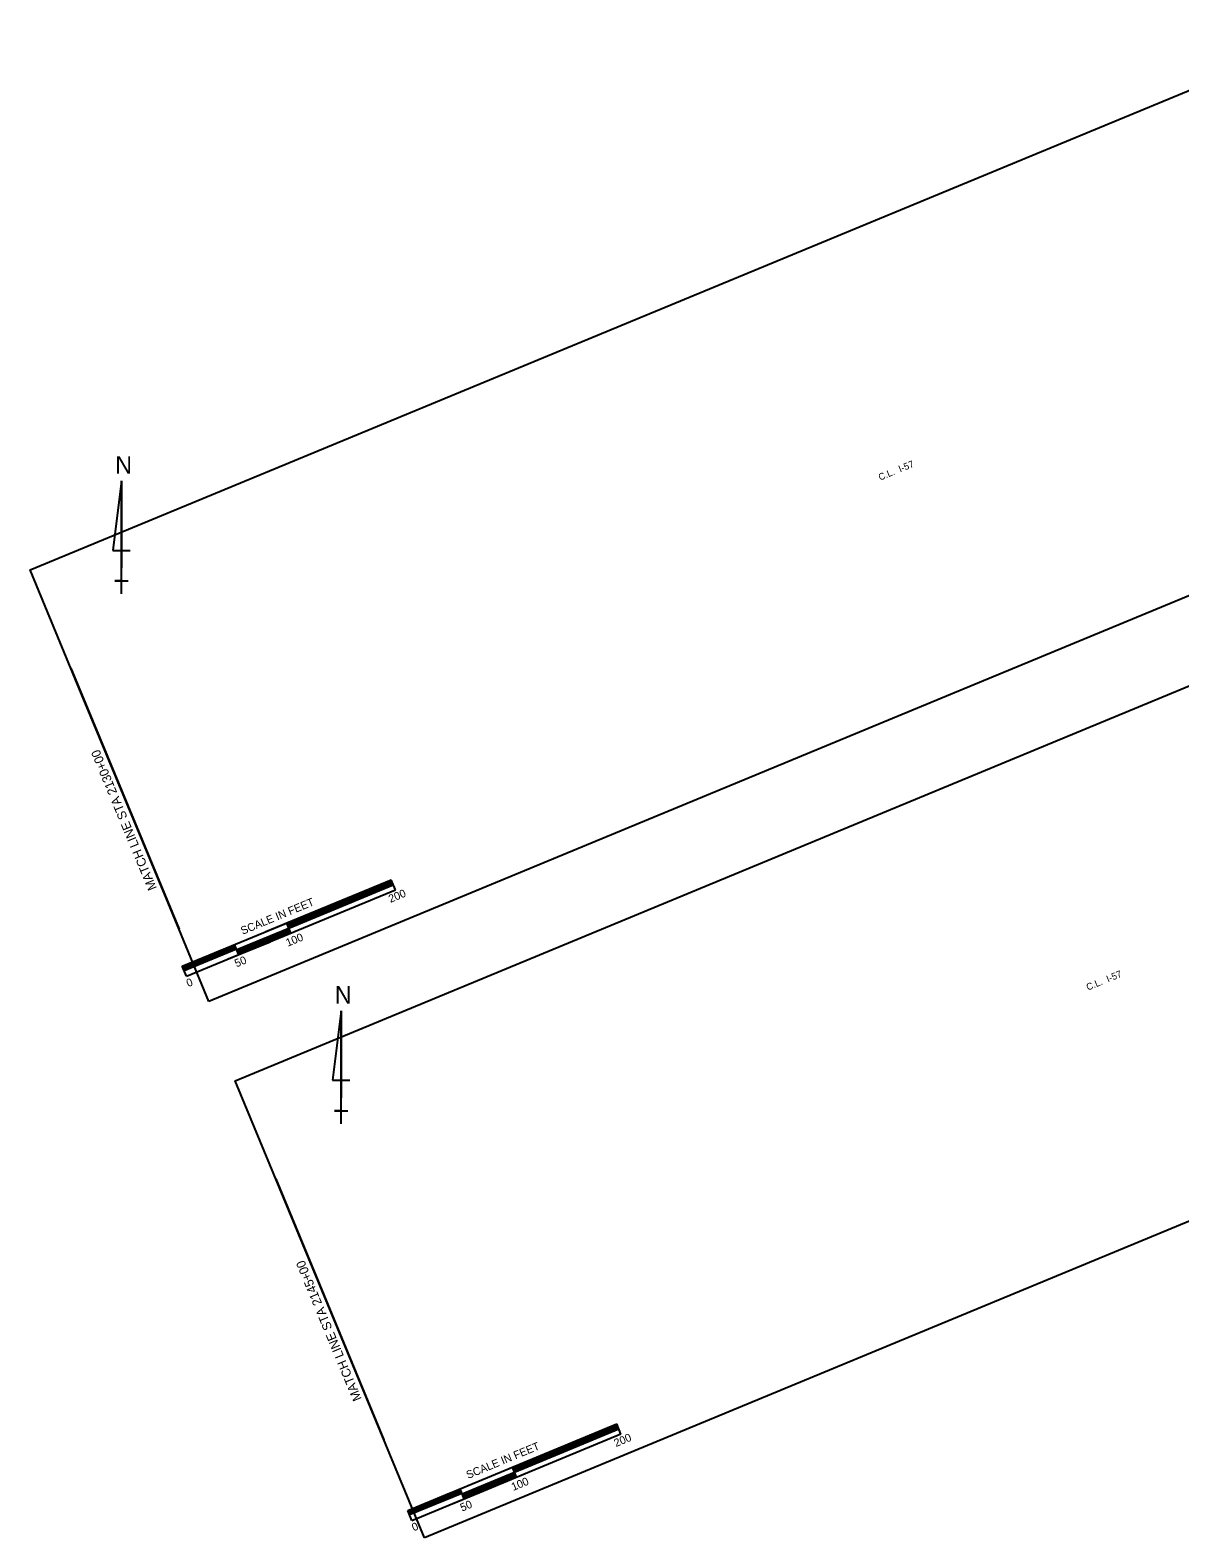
# Model space of a CAD drawing. Extents: x 1718926 to 1720959, y 766362 to 768034.
# Drawn here: x 1718926 to 1719943, y 766362 to 767696 of the extents above; entities that cross this region are included whole.
import ezdxf

# ---------------------------------------------------------------- set-up
doc = ezdxf.new("R2010")
doc.units = 0
for name, color, linetype in [('19', 7, 'Continuous'), ('2', 7, 'Continuous'), ('20', 7, 'Continuous'), ('3', 7, 'Continuous'), ('5', 7, 'Continuous')]:
    doc.layers.add(name, color=color, linetype=linetype)

msp = doc.modelspace()

# ---------------------------------------------------------------- linework, layer by layer
at = {"layer": '19'}
for p, q in [((1718961.8, 767131.7), (1719057.5, 766900.8)), ((1719143, 766679.8), (1719238.7, 766448.9))]:
    msp.add_line(p, q, dxfattribs=at)
at = {"layer": '2'}
for points in [[(1719084, 766836.7), (1719047.9, 766923.9), (1718971.4, 767108.6), (1718925.9, 767218.5), (1720031.8, 767676.5), (1720208.6, 767696.1), (1720357.2, 767682.7), (1720433.7, 767497.9), (1720473.4, 767413.9), (1720476, 767413.2)], [(1719274.6, 766362.1), (1719107.1, 766766.6), (1720213, 767224.6), (1720510, 767294), (1720538.4, 767230.8), (1720615, 767046), (1720666.6, 766938.7)]]:
    msp.add_lwpolyline(points, close=True, dxfattribs=at)
at = {"layer": '20'}
for p, q in [((1719134.3, 766898.5), (1719245.2, 766944.4)), ((1719153.1, 766905.4), (1719245.5, 766943.7)), ((1719153.4, 766904.7), (1719245.8, 766942.9)), ((1719153.7, 766903.9), (1719246.1, 766942.2)), ((1719154, 766903.2), (1719246.4, 766941.5)), ((1719154.3, 766902.5), (1719246.7, 766940.7)), ((1719154.7, 766901.7), (1719247, 766940)), ((1719248.9, 766935.5), (1719245.2, 766944.4)), ((1719060.4, 766867.9), (1719208.2, 766929.1)), ((1719064.1, 766859), (1719248.9, 766935.6)), ((1719154.7, 766901.7), (1719210.1, 766924.7)), ((1719108.5, 766882.6), (1719154.7, 766901.7)), ((1719108.8, 766881.8), (1719155, 766901)), ((1719109.1, 766881.1), (1719155.3, 766900.2)), ((1719109.4, 766880.4), (1719155.6, 766899.5)), ((1719109.7, 766879.6), (1719155.9, 766898.8)), ((1719156.5, 766897.3), (1719152.8, 766906.1)), ((1719060.7, 766867.1), (1719106.9, 766886.3)), ((1719061, 766866.4), (1719107.2, 766885.5)), ((1719101.1, 766874.3), (1719138, 766889.6)), ((1719110.3, 766878.1), (1719106.6, 766887)), ((1719110, 766878.9), (1719156.2, 766898)), ((1719060.4, 766867.9), (1719097.4, 766883.2)), ((1719061.3, 766865.7), (1719107.5, 766884.8)), ((1719061.7, 766864.9), (1719107.8, 766884.1)), ((1719062, 766864.2), (1719108.2, 766883.3)), ((1719064.1, 766859), (1719060.4, 766867.9)), ((1719333.8, 766417), (1719444.6, 766462.9)), ((1719352.6, 766423.9), (1719445, 766462.2)), ((1719352.9, 766423.2), (1719445.3, 766461.5)), ((1719353.2, 766422.4), (1719445.6, 766460.7)), ((1719353.5, 766421.7), (1719445.9, 766460)), ((1719353.8, 766421), (1719446.2, 766459.2)), ((1719354.1, 766420.2), (1719446.5, 766458.5)), ((1719448.3, 766454), (1719444.7, 766462.9)), ((1719259.9, 766386.4), (1719407.7, 766447.6)), ((1719263.5, 766377.5), (1719448.3, 766454.1)), ((1719354.1, 766420.2), (1719409.5, 766443.2)), ((1719307.9, 766401.1), (1719354.1, 766420.2)), ((1719308.2, 766400.4), (1719354.4, 766419.5)), ((1719308.5, 766399.6), (1719354.7, 766418.8)), ((1719355.9, 766415.8), (1719352.3, 766424.7)), ((1719300.5, 766392.8), (1719337.5, 766408.1)), ((1719309.7, 766396.7), (1719306.1, 766405.5)), ((1719308.8, 766398.9), (1719355, 766418)), ((1719309.1, 766398.1), (1719355.3, 766417.3)), ((1719309.4, 766397.4), (1719355.6, 766416.5)), ((1719259.9, 766386.4), (1719296.8, 766401.7)), ((1719260.2, 766385.7), (1719306.4, 766404.8)), ((1719260.5, 766384.9), (1719306.7, 766404.1)), ((1719260.8, 766384.2), (1719307, 766403.3)), ((1719261.1, 766383.4), (1719307.3, 766402.6)), ((1719261.4, 766382.7), (1719307.6, 766401.8)), ((1719263.5, 766377.5), (1719259.9, 766386.4))]:
    msp.add_line(p, q, dxfattribs=at)
at = {"layer": '3'}
for p, q in [((1719006.7, 767297.4), (1718999, 767235.8)), ((1719006.7, 767197.4), (1719006.7, 767297.4)), ((1719006.7, 767297.4), (1719006.7, 767220.5)), ((1718999, 767235.8), (1719014.4, 767235.8)), ((1719006.7, 767197.4), (1719006.7, 767220.5)), ((1719006.7, 767208.9), (1719000.9, 767208.9)), ((1719000.9, 767208.9), (1719012.5, 767208.9)), ((1719006.7, 767197.4), (1719006.7, 767208.9)), ((1719200.9, 766828.5), (1719193.2, 766767)), ((1719200.9, 766728.5), (1719200.9, 766828.5)), ((1719200.9, 766828.5), (1719200.9, 766751.6)), ((1719193.2, 766767), (1719208.6, 766767)), ((1719200.9, 766740.1), (1719195.1, 766740.1)), ((1719195.1, 766740.1), (1719206.7, 766740.1)), ((1719200.9, 766728.5), (1719200.9, 766751.6)), ((1719200.9, 766728.5), (1719200.9, 766740.1))]:
    msp.add_line(p, q, dxfattribs=at)

# ---------------------------------------------------------------- texts
at = {"layer": '19'}
for s, p in [('MATCH LINE STA 2130+00', (1719038, 766937)), ('MATCH LINE STA 2145+00', (1719219.2, 766485.1))]:
    msp.add_text(s, height=8, rotation=112.5, dxfattribs=at).set_placement(p)
at = {"layer": '20'}
for s, height, p in [('SCALE IN FEET', 7.001, (1719113.8, 766895.7)), ('200', 7, (1719244.5, 766923.9)), ('100', 7, (1719153.7, 766885.1)), ('50', 7, (1719108.4, 766866.8)), ('0', 7, (1719065.7, 766849.3)), ('SCALE IN FEET', 7.001, (1719313.2, 766414.2)), ('200', 7, (1719443.9, 766442.4)), ('100', 7, (1719353.1, 766403.6)), ('50', 7, (1719307.9, 766385.3)), ('0', 7, (1719265.1, 766367.8))]:
    msp.add_text(s, height=height, rotation=22.5003, dxfattribs=at).set_placement(p)
at = {"layer": '3'}
for p in [(1719001.1, 767303.8), (1719195.3, 766834.9)]:
    msp.add_text('N', height=15.4, rotation=360, dxfattribs=at).set_placement(p)
at = {"layer": '5'}
for p in [(1719677.5, 767297.5), (1719861.3, 766846.3)]:
    msp.add_text('C.L.  I-57', height=6, rotation=22.3523, dxfattribs=at).set_placement(p)

doc.saveas('drawing.dxf')
